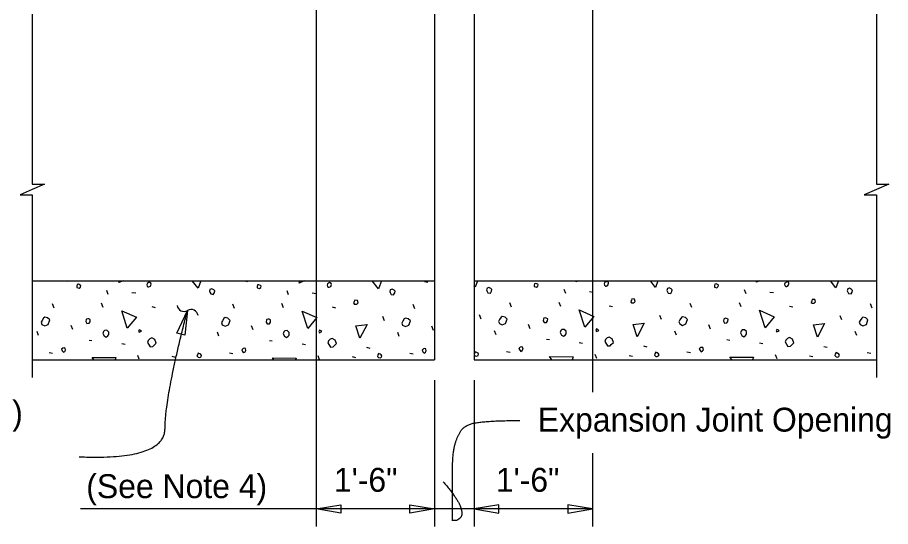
# Model space of a CAD drawing. Extents: x 0.4 to 38.5, y 1.2 to 25.4.
# Drawn here: x 23.59 to 30.96, y 12.63 to 16.93 of the extents above; entities that cross this region are included whole.
import ezdxf

# ---------------------------------------------------------------- set-up
doc = ezdxf.new("R2010")
doc.units = 0
for name, color, linetype in [('CL_Major', 7, 'Continuous'), ('Dimension', 7, 'Continuous'), ('Miscellaneous', 7, 'Continuous'), ('SupstrConc', 7, 'Continuous'), ('TextStructures', 7, 'Continuous')]:
    doc.layers.add(name, color=color, linetype=linetype)

msp = doc.modelspace()

# ---------------------------------------------------------------- linework, layer by layer
at = {"layer": 'CL_Major'}
for p, q in [((26.1118, 25.3255), (26.1118, 12.6331)), ((28.4451, 25.3255), (28.4451, 13.7657)), ((28.4451, 13.2526), (28.4451, 12.6331))]:
    msp.add_line(p, q, dxfattribs=at)
at = {"layer": 'Dimension'}
for p, q in [((27.1118, 13.8672), (27.1118, 12.6331)), ((27.4452, 13.8672), (27.4452, 12.6331)), ((28.4451, 12.7811), (26.1118, 12.7811))]:
    msp.add_line(p, q, dxfattribs=at)
for points in [[(23.712, 16.9573), (23.712, 15.5233), (23.8153, 15.5233), (23.712, 15.4783), (23.6086, 15.4333), (23.712, 15.4333), (23.712, 13.8908)], [(30.845, 16.9573), (30.845, 15.5233), (30.9484, 15.5233), (30.845, 15.4783), (30.7417, 15.4333), (30.845, 15.4333), (30.845, 13.8908)]]:
    msp.add_lwpolyline(points, dxfattribs=at)
for points in [[(25.0235, 14.4569), (25.0013, 14.2468), (24.9333, 14.2659)], [(26.1118, 12.7812), (26.3201, 12.8165), (26.3201, 12.746)], [(27.1118, 12.7812), (26.9036, 12.746), (26.9036, 12.8165)], [(27.4452, 12.7812), (27.6534, 12.746), (27.6534, 12.8165)], [(28.4452, 12.7812), (28.2369, 12.8165), (28.2369, 12.746)]]:
    msp.add_lwpolyline(points, close=True, dxfattribs=at)
for centre, start, end in [((24.9944, 14.508), 188.42943, 300.15665), ((25.0543, 14.4049), 8.42943, 120.15665)]:
    msp.add_arc(centre, 0.0596, start, end, dxfattribs=at)
for points in [[(24.107, 13.2213), (24.8329, 13.1916), (24.8345, 13.7279), (25.0236, 14.4567)], [(27.1848, 13.0096), (27.3029, 12.8733), (27.3543, 12.734), (27.3059, 12.6826), (27.2628, 12.6826), (27.2628, 12.6826), (27.2628, 12.9339), (27.2628, 13.2367), (27.2938, 13.373), (27.3664, 13.4972), (27.5995, 13.5274), (27.8326, 13.5274)]]:
    msp.add_open_spline(points, degree=2, dxfattribs=at)
at = {"layer": 'Miscellaneous'}
for p, q in [((23.9875, 14.7072), (24.0062, 14.7035)), ((25.5035, 14.7053), (25.53, 14.7)), ((27.0273, 14.7017), (27.0539, 14.6964)), ((29.3939, 14.7072), (29.395, 14.707)), ((24.3545, 14.5921), (24.3421, 14.6257)), ((24.5542, 14.608), (24.5861, 14.6045)), ((25.8783, 14.5886), (25.8659, 14.6222)), ((28.2194, 14.5992), (28.2071, 14.6328)), ((28.4192, 14.6151), (28.451, 14.6116)), ((29.7432, 14.5957), (29.7309, 14.6292)), ((29.943, 14.6116), (29.9748, 14.608)), ((26.0781, 14.6045), (26.1099, 14.601)), ((23.8966, 14.4772), (23.8825, 14.5126)), ((24.3121, 14.4825), (24.2979, 14.5179)), ((24.7222, 14.4896), (24.7505, 14.4825)), ((25.4204, 14.4737), (25.4063, 14.509)), ((25.8359, 14.479), (25.8217, 14.5143)), ((26.246, 14.4861), (26.2743, 14.479)), ((26.9443, 14.4701), (26.9301, 14.5055)), ((27.7616, 14.4843), (27.7474, 14.5196)), ((28.177, 14.4896), (28.1629, 14.5249)), ((28.5871, 14.4967), (28.6154, 14.4896)), ((29.2854, 14.4807), (29.2713, 14.5161)), ((29.7008, 14.4861), (29.6867, 14.5214)), ((30.1109, 14.4931), (30.1392, 14.4861)), ((30.8092, 14.4772), (30.7951, 14.5126)), ((26.6879, 14.3694), (26.6738, 14.4047)), ((27.5053, 14.3835), (27.4911, 14.4189)), ((29.0291, 14.38), (29.0149, 14.4153)), ((30.5529, 14.3765), (30.5387, 14.4118)), ((24.054, 14.2951), (24.0398, 14.3305)), ((25.5778, 14.2916), (25.5636, 14.327)), ((27.1016, 14.2881), (27.0874, 14.3234)), ((27.9189, 14.3022), (27.9048, 14.3376)), ((29.4427, 14.2987), (29.4286, 14.334)), ((23.7658, 14.2439), (23.7534, 14.2775)), ((25.2896, 14.2403), (25.2773, 14.2739)), ((26.8134, 14.2368), (26.8011, 14.2704)), ((27.6308, 14.2509), (27.6184, 14.2845)), ((29.1546, 14.2474), (29.1422, 14.281)), ((30.6784, 14.2439), (30.666, 14.2775)), ((24.1918, 14.2067), (24.2166, 14.2032)), ((24.4676, 14.1785), (24.4977, 14.1732)), ((25.7157, 14.2032), (25.7404, 14.1997)), ((25.9914, 14.1749), (26.0215, 14.1696)), ((28.0568, 14.2138), (28.0815, 14.2103)), ((28.3326, 14.1855), (28.3626, 14.1802)), ((29.5806, 14.2103), (29.6054, 14.2067)), ((29.8564, 14.182), (29.8864, 14.1767)), ((23.8542, 14.1024), (23.8843, 14.0971)), ((25.378, 14.0989), (25.4081, 14.0936)), ((26.5359, 14.1466), (26.5642, 14.1396)), ((26.9018, 14.0954), (26.9319, 14.0901)), ((27.7192, 14.1095), (27.7492, 14.1042)), ((28.877, 14.1572), (28.9053, 14.1502)), ((29.243, 14.106), (29.273, 14.1007)), ((30.4009, 14.1537), (30.4291, 14.1466)), ((30.7668, 14.1024), (30.7968, 14.0971)), ((24.6161, 14.0441), (24.6037, 14.0777)), ((24.8901, 14.0706), (24.9184, 14.0636)), ((26.1399, 14.0406), (26.1275, 14.0742)), ((26.4139, 14.0671), (26.4422, 14.06)), ((28.4811, 14.0512), (28.4687, 14.0848)), ((28.7551, 14.0777), (28.7833, 14.0706)), ((30.0049, 14.0476), (29.9925, 14.0812)), ((30.2789, 14.0742), (30.3072, 14.0671))]:
    msp.add_line(p, q, dxfattribs=at)
for points in [[(24.4429, 14.6911), (24.4478, 14.7072)], [(24.4788, 14.7072), (24.4429, 14.6911)], [(24.6904, 14.6558), (24.6974, 14.6558), (24.7116, 14.6628), (24.7169, 14.6787), (24.7151, 14.6876), (24.701, 14.6946), (24.6833, 14.684), (24.6797, 14.6734), (24.6833, 14.6628), (24.6904, 14.6558)], [(25.1129, 14.6434), (25.0643, 14.7072)], [(25.1367, 14.7072), (25.1129, 14.6434)], [(25.9667, 14.6876), (25.9727, 14.7072)], [(26.0105, 14.7072), (25.9667, 14.6876)], [(26.2142, 14.6522), (26.2212, 14.6522), (26.2354, 14.6593), (26.2407, 14.6752), (26.2389, 14.684), (26.2248, 14.6911), (26.2071, 14.6805), (26.2036, 14.6699), (26.2071, 14.6593), (26.2142, 14.6522)], [(26.6367, 14.6398), (26.5854, 14.7072)], [(26.6619, 14.7072), (26.6367, 14.6398)], [(27.4739, 14.7072), (27.454, 14.654)], [(27.9525, 14.6575), (27.9719, 14.6522), (27.9843, 14.6611), (27.9861, 14.6734), (27.9826, 14.677), (27.9684, 14.684), (27.956, 14.6823), (27.9543, 14.6699), (27.9525, 14.6575)], [(28.3078, 14.6982), (28.3106, 14.7072)], [(28.328, 14.7072), (28.3078, 14.6982)], [(28.5553, 14.6628), (28.5624, 14.6628), (28.5765, 14.6699), (28.5818, 14.6858), (28.5801, 14.6946), (28.5659, 14.7017), (28.5482, 14.6911), (28.5447, 14.6805), (28.5482, 14.6699), (28.5553, 14.6628)], [(28.9778, 14.6505), (28.9346, 14.7072)], [(28.999, 14.7072), (28.9778, 14.6505)], [(29.8316, 14.6946), (29.8355, 14.7072)], [(29.8597, 14.7072), (29.8316, 14.6946)], [(30.0791, 14.6593), (30.0862, 14.6593), (30.1003, 14.6664), (30.1056, 14.6823), (30.1039, 14.6911), (30.0897, 14.6982), (30.0721, 14.6876), (30.0685, 14.677), (30.0721, 14.6664), (30.0791, 14.6593)], [(30.5016, 14.6469), (30.4558, 14.7072)], [(30.5242, 14.7072), (30.5016, 14.6469)], [(24.0875, 14.6505), (24.107, 14.6452), (24.1194, 14.654), (24.1211, 14.6664), (24.1176, 14.6699), (24.1035, 14.677), (24.0911, 14.6752), (24.0893, 14.6628), (24.0875, 14.6505)], [(25.2118, 14.6116), (25.2207, 14.5957), (25.2419, 14.5921), (25.2507, 14.608), (25.2543, 14.6222), (25.2454, 14.631), (25.2295, 14.6398), (25.2136, 14.6345), (25.2083, 14.6186), (25.2118, 14.6116)], [(25.6114, 14.6469), (25.6308, 14.6416), (25.6432, 14.6505), (25.6449, 14.6628), (25.6414, 14.6664), (25.6273, 14.6734), (25.6149, 14.6717), (25.6131, 14.6593), (25.6114, 14.6469)], [(26.7357, 14.608), (26.7445, 14.5921), (26.7657, 14.5886), (26.7746, 14.6045), (26.7781, 14.6186), (26.7692, 14.6275), (26.7533, 14.6363), (26.7374, 14.631), (26.7321, 14.6151), (26.7357, 14.608)], [(27.454, 14.654), (27.4451, 14.6656)], [(27.553, 14.6222), (27.5618, 14.6063), (27.583, 14.6027), (27.5919, 14.6186), (27.5954, 14.6328), (27.5866, 14.6416), (27.5707, 14.6505), (27.5548, 14.6452), (27.5494, 14.6292), (27.553, 14.6222)], [(29.0768, 14.6186), (29.0856, 14.6027), (29.1069, 14.5992), (29.1157, 14.6151), (29.1192, 14.6292), (29.1104, 14.6381), (29.0945, 14.6469), (29.0786, 14.6416), (29.0733, 14.6257), (29.0768, 14.6186)], [(29.4763, 14.654), (29.4958, 14.6487), (29.5081, 14.6575), (29.5099, 14.6699), (29.5064, 14.6734), (29.4922, 14.6805), (29.4798, 14.6787), (29.4781, 14.6664), (29.4763, 14.654)], [(30.6006, 14.6151), (30.6095, 14.5992), (30.6307, 14.5957), (30.6395, 14.6116), (30.643, 14.6257), (30.6342, 14.6345), (30.6183, 14.6434), (30.6024, 14.6381), (30.5971, 14.6222), (30.6006, 14.6151)], [(26.4334, 14.5108), (26.4546, 14.5108), (26.4652, 14.5214), (26.4599, 14.5409), (26.4369, 14.5426), (26.4334, 14.532), (26.4281, 14.5232), (26.4334, 14.5108), (26.4298, 14.5143)], [(28.7745, 14.5214), (28.7957, 14.5214), (28.8063, 14.532), (28.801, 14.5515), (28.778, 14.5532), (28.7745, 14.5426), (28.7692, 14.5338), (28.7745, 14.5214), (28.771, 14.5249)], [(30.2983, 14.5179), (30.3195, 14.5179), (30.3301, 14.5285), (30.3248, 14.5479), (30.3019, 14.5497), (30.2983, 14.5391), (30.293, 14.5302), (30.2983, 14.5179), (30.2948, 14.5214)], [(28.3803, 14.3146), (28.3326, 14.4613), (28.4581, 14.4065), (28.3803, 14.3146)], [(23.7941, 14.3393), (23.8171, 14.327), (23.8471, 14.3393), (23.8595, 14.3765), (23.8418, 14.3941), (23.8188, 14.3994), (23.8082, 14.3924), (23.7959, 14.3729), (23.787, 14.357), (23.7941, 14.3393)], [(24.1636, 14.3623), (24.1724, 14.3464), (24.1918, 14.3482), (24.2007, 14.3605), (24.2025, 14.38), (24.1901, 14.3853), (24.1812, 14.3871), (24.1706, 14.3835), (24.1671, 14.38), (24.1636, 14.3623)], [(24.5153, 14.3075), (24.4676, 14.4542), (24.5931, 14.3994), (24.5153, 14.3075)], [(25.3179, 14.3358), (25.3409, 14.3234), (25.3709, 14.3358), (25.3833, 14.3729), (25.3656, 14.3906), (25.3427, 14.3959), (25.3321, 14.3888), (25.3197, 14.3694), (25.3108, 14.3535), (25.3179, 14.3358)], [(26.0392, 14.304), (25.9914, 14.4507), (26.1169, 14.3959), (26.0392, 14.304)], [(26.8417, 14.3323), (26.8647, 14.3199), (26.8948, 14.3323), (26.9071, 14.3694), (26.8895, 14.3871), (26.8665, 14.3924), (26.8559, 14.3853), (26.8435, 14.3658), (26.8347, 14.3499), (26.8417, 14.3323)], [(27.659, 14.3464), (27.682, 14.334), (27.7121, 14.3464), (27.7245, 14.3835), (27.7068, 14.4012), (27.6838, 14.4065), (27.6732, 14.3994), (27.6608, 14.38), (27.652, 14.3641), (27.659, 14.3464)], [(28.0285, 14.3694), (28.0374, 14.3535), (28.0568, 14.3552), (28.0656, 14.3676), (28.0674, 14.3871), (28.055, 14.3924), (28.0462, 14.3941), (28.0356, 14.3906), (28.032, 14.3871), (28.0285, 14.3694)], [(29.1829, 14.3429), (29.2058, 14.3305), (29.2359, 14.3429), (29.2483, 14.38), (29.2306, 14.3977), (29.2076, 14.403), (29.197, 14.3959), (29.1846, 14.3765), (29.1758, 14.3605), (29.1829, 14.3429)], [(29.5523, 14.3658), (29.5612, 14.3499), (29.5806, 14.3517), (29.5895, 14.3641), (29.5912, 14.3835), (29.5788, 14.3888), (29.57, 14.3906), (29.5594, 14.3871), (29.5559, 14.3835), (29.5523, 14.3658)], [(29.9041, 14.311), (29.8564, 14.4578), (29.9819, 14.403), (29.9041, 14.311)], [(30.7067, 14.3393), (30.7297, 14.327), (30.7597, 14.3393), (30.7721, 14.3765), (30.7544, 14.3941), (30.7314, 14.3994), (30.7208, 14.3924), (30.7084, 14.3729), (30.6996, 14.357), (30.7067, 14.3393)], [(25.6874, 14.3588), (25.6962, 14.3429), (25.7157, 14.3446), (25.7245, 14.357), (25.7263, 14.3765), (25.7139, 14.3818), (25.7051, 14.3835), (25.6944, 14.38), (25.6909, 14.3765), (25.6874, 14.3588)], [(26.4811, 14.2227), (26.4475, 14.327), (26.5412, 14.3393), (26.4811, 14.2227)], [(28.8222, 14.2333), (28.7887, 14.3376), (28.8823, 14.3499), (28.8222, 14.2333)], [(30.3461, 14.2297), (30.3125, 14.334), (30.4062, 14.3464), (30.3461, 14.2297)], [(24.3085, 14.2633), (24.3191, 14.2421), (24.3368, 14.2315), (24.3509, 14.2421), (24.358, 14.2527), (24.358, 14.2739), (24.3421, 14.2898), (24.3227, 14.2881), (24.3138, 14.2792), (24.3085, 14.2633)], [(24.6143, 14.2722), (24.6338, 14.281), (24.6267, 14.2881), (24.6143, 14.2934), (24.609, 14.281), (24.6143, 14.2722)], [(25.8323, 14.2598), (25.8429, 14.2386), (25.8606, 14.228), (25.8748, 14.2386), (25.8818, 14.2492), (25.8818, 14.2704), (25.8659, 14.2863), (25.8465, 14.2845), (25.8376, 14.2757), (25.8323, 14.2598)], [(26.1382, 14.2686), (26.1576, 14.2775), (26.1505, 14.2845), (26.1382, 14.2898), (26.1329, 14.2775), (26.1382, 14.2686)], [(28.1735, 14.2704), (28.1841, 14.2492), (28.2018, 14.2386), (28.2159, 14.2492), (28.223, 14.2598), (28.223, 14.281), (28.2071, 14.2969), (28.1876, 14.2951), (28.1788, 14.2863), (28.1735, 14.2704)], [(28.4793, 14.2792), (28.4987, 14.2881), (28.4917, 14.2951), (28.4793, 14.3004), (28.474, 14.2881), (28.4793, 14.2792)], [(29.6973, 14.2668), (29.7079, 14.2456), (29.7256, 14.235), (29.7397, 14.2456), (29.7468, 14.2562), (29.7468, 14.2775), (29.7309, 14.2934), (29.7114, 14.2916), (29.7026, 14.2828), (29.6973, 14.2668)], [(30.0031, 14.2757), (30.0226, 14.2845), (30.0155, 14.2916), (30.0031, 14.2969), (29.9978, 14.2845), (30.0031, 14.2757)], [(24.6851, 14.1873), (24.708, 14.1502), (24.731, 14.1519), (24.7399, 14.1608), (24.7593, 14.1802), (24.7469, 14.2103), (24.7222, 14.2244), (24.7045, 14.2174), (24.6904, 14.2032), (24.6851, 14.1873)], [(26.2089, 14.1838), (26.2318, 14.1466), (26.2548, 14.1484), (26.2637, 14.1572), (26.2831, 14.1767), (26.2707, 14.2067), (26.246, 14.2209), (26.2283, 14.2138), (26.2142, 14.1997), (26.2089, 14.1838)], [(28.55, 14.1944), (28.573, 14.1572), (28.596, 14.159), (28.6048, 14.1679), (28.6242, 14.1873), (28.6119, 14.2174), (28.5871, 14.2315), (28.5694, 14.2244), (28.5553, 14.2103), (28.55, 14.1944)], [(30.0738, 14.1908), (30.0968, 14.1537), (30.1198, 14.1555), (30.1286, 14.1643), (30.1481, 14.1838), (30.1357, 14.2138), (30.1109, 14.228), (30.0933, 14.2209), (30.0791, 14.2067), (30.0738, 14.1908)], [(23.9656, 14.1148), (23.9762, 14.1042), (23.9868, 14.1113), (23.9939, 14.1219), (23.9903, 14.1396), (23.9815, 14.1413), (23.9691, 14.1396), (23.9585, 14.129), (23.9656, 14.1148)], [(25.1146, 14.0618), (25.127, 14.06), (25.1394, 14.0653), (25.1429, 14.0759), (25.1376, 14.0848), (25.127, 14.0918), (25.1146, 14.0971), (25.1075, 14.083), (25.104, 14.0724), (25.1146, 14.0618)], [(25.4894, 14.1113), (25.5, 14.1007), (25.5106, 14.1077), (25.5177, 14.1184), (25.5141, 14.136), (25.5053, 14.1378), (25.4929, 14.136), (25.4823, 14.1254), (25.4894, 14.1113)], [(26.6384, 14.0583), (26.6508, 14.0565), (26.6632, 14.0618), (26.6667, 14.0724), (26.6614, 14.0812), (26.6508, 14.0883), (26.6384, 14.0936), (26.6314, 14.0795), (26.6278, 14.0689), (26.6384, 14.0583)], [(27.0132, 14.1077), (27.0238, 14.0971), (27.0344, 14.1042), (27.0415, 14.1148), (27.0379, 14.1325), (27.0291, 14.1343), (27.0167, 14.1325), (27.0061, 14.1219), (27.0132, 14.1077)], [(27.4558, 14.0724), (27.4681, 14.0706), (27.4805, 14.0759), (27.484, 14.0865), (27.4787, 14.0954), (27.4681, 14.1024), (27.4558, 14.1077), (27.4487, 14.0936), (27.4451, 14.083), (27.4558, 14.0724)], [(27.8305, 14.1219), (27.8411, 14.1113), (27.8517, 14.1184), (27.8588, 14.129), (27.8553, 14.1466), (27.8464, 14.1484), (27.8341, 14.1466), (27.8235, 14.136), (27.8305, 14.1219)], [(28.9796, 14.0689), (28.9919, 14.0671), (29.0043, 14.0724), (29.0079, 14.083), (29.0026, 14.0918), (28.9919, 14.0989), (28.9796, 14.1042), (28.9725, 14.0901), (28.969, 14.0795), (28.9796, 14.0689)], [(29.3543, 14.1184), (29.3649, 14.1077), (29.3756, 14.1148), (29.3826, 14.1254), (29.3791, 14.1431), (29.3702, 14.1449), (29.3579, 14.1431), (29.3473, 14.1325), (29.3543, 14.1184)], [(30.5034, 14.0653), (30.5158, 14.0636), (30.5281, 14.0689), (30.5317, 14.0795), (30.5264, 14.0883), (30.5158, 14.0954), (30.5034, 14.1007), (30.4963, 14.0865), (30.4928, 14.0759), (30.5034, 14.0653)], [(24.2331, 14.0406), (24.2184, 14.06), (24.4181, 14.0583), (24.4115, 14.0406)], [(25.7543, 14.0406), (25.7422, 14.0565), (25.9419, 14.0547), (25.9366, 14.0406)], [(28.1035, 14.0406), (28.0833, 14.0671), (28.2831, 14.0653), (28.2738, 14.0406)], [(29.6246, 14.0406), (29.6071, 14.0636), (29.8069, 14.0618), (29.799, 14.0406)]]:
    msp.add_lwpolyline(points, dxfattribs=at)
at = {"layer": 'SupstrConc'}
for p, q in [((27.1118, 16.9573), (27.1118, 14.0406)), ((27.4451, 16.9573), (27.4451, 14.0406)), ((23.712, 14.7072), (27.1118, 14.7072)), ((27.4451, 14.7072), (30.845, 14.7072)), ((23.712, 14.0406), (27.1118, 14.0406)), ((27.4451, 14.0406), (30.845, 14.0406))]:
    msp.add_line(p, q, dxfattribs=at)
at = {"layer": 'TextStructures'}
msp.add_line((26.1118, 12.7812), (24.1193, 12.7812), dxfattribs=at)

# ---------------------------------------------------------------- texts
at = {"layer": 'Dimension'}
msp.add_text('Bridge Deck (shown)', height=0.2016, dxfattribs=at).set_placement((21.1302, 13.4931))
at = {"layer": 'TextStructures'}
for s, p in [('Expansion Joint Opening', (27.9841, 13.4341)), ('(See Note 4)', (24.1684, 12.8728)), ('1\'-6"', (26.2611, 12.9264)), ('1\'-6"', (27.6293, 12.9264))]:
    msp.add_text(s, height=0.2016, dxfattribs=at).set_placement(p)

doc.saveas('drawing.dxf')
